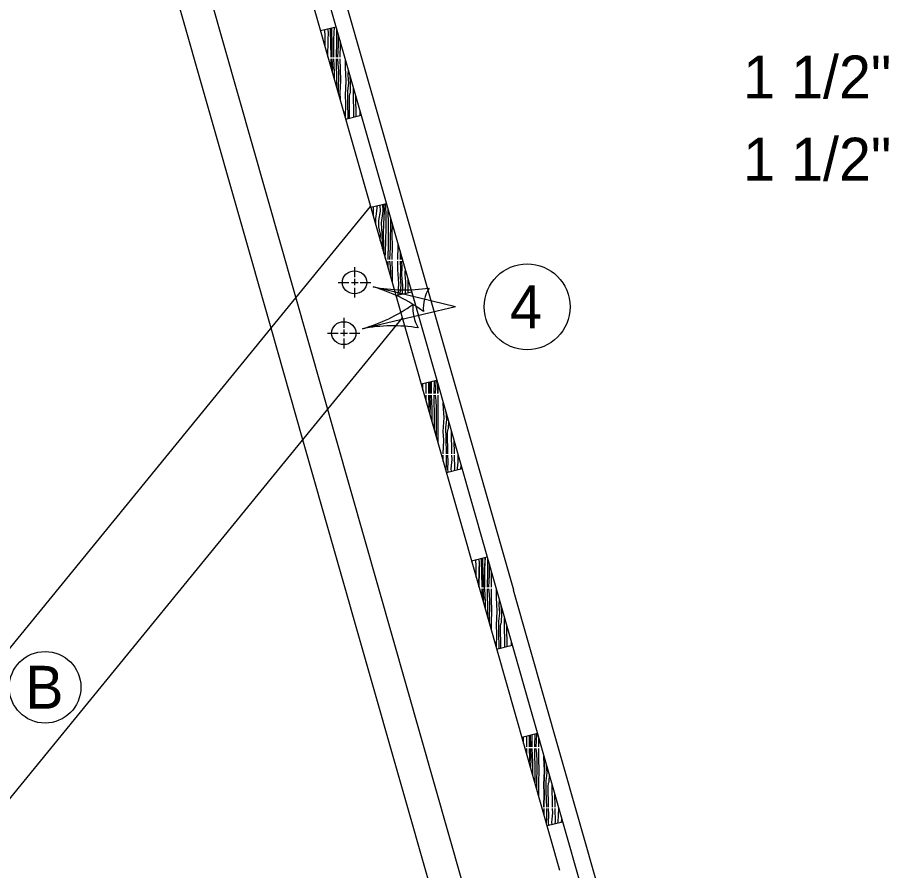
# Model space of a CAD drawing. Extents: x 49991.4 to 50021, y 49987.6 to 50011.4.
# Drawn here: x 50013.065 to 50014.286, y 49993.859 to 49995.05 of the extents above; entities that cross this region are included whole.
import ezdxf

# ---------------------------------------------------------------- set-up
doc = ezdxf.new("R2010")
doc.units = 0
for name, color, linetype in [('Level 1', 7, 'Continuous'), ('Level 2', 7, 'Continuous'), ('Level 3', 7, 'Continuous'), ('Level 33', 7, 'Continuous'), ('Level 4', 7, 'Continuous'), ('Level 5', 7, 'Continuous')]:
    doc.layers.add(name, color=color, linetype=linetype)

msp = doc.modelspace()

# ---------------------------------------------------------------- linework, layer by layer
at = {"layer": 'Level 1'}
for p, q in [((50013.7582, 49994.2501), (50013.1042, 49996.5446)), ((50013.6869, 49993.8419), (50012.9235, 49996.5211)), ((50013.7112, 49994.2501), (50013.0664, 49996.5131)), ((50013.4195, 49994.6162), (50013.1179, 49995.6741)), ((50013.6196, 49994.654), (50013.4039, 49995.411)), ((50013.4884, 49995.032), (50013.5102, 49995.0375)), ((50013.5235, 49994.9085), (50013.5453, 49994.9141)), ((50013.5587, 49994.7852), (50013.5804, 49994.7906)), ((50013.7346, 49994.2501), (50013.6148, 49994.6706)), ((50012.3964, 49993.3626), (50013.4541, 49994.6588)), ((50013.5938, 49994.6618), (50013.6157, 49994.6673)), ((50013.5938, 49994.6618), (50013.6157, 49994.6673)), ((50013.629, 49994.5384), (50013.6508, 49994.5439)), ((50012.5552, 49993.3474), (50013.4984, 49994.5032)), ((50013.6869, 49993.6773), (50013.4637, 49994.4605)), ((50013.6642, 49994.4149), (50013.686, 49994.4205)), ((50013.6992, 49994.2915), (50013.7211, 49994.297)), ((50013.7344, 49994.168), (50013.7562, 49994.1736)), ((50013.7696, 49994.0448), (50013.7913, 49994.0503)), ((50013.9188, 49993.6855), (50013.8228, 49994.0228)), ((50013.8047, 49993.9213), (50013.8265, 49993.9268)), ((50013.897, 49993.68), (50013.8257, 49993.9301))]:
    msp.add_line(p, q, dxfattribs=at)
for points in [[(50013.4988, 49994.9954), (50013.4992, 49995.0185), (50013.4994, 49995.0301), (50013.4987, 49995.0346)], [(50013.5018, 49995.0354), (50013.502, 49995.0307), (50013.5024, 49995.0149), (50013.5026, 49994.9949)], [(50013.5039, 49995.0359), (50013.5039, 49995.0307), (50013.5042, 49995.0149), (50013.5044, 49994.9949)], [(50013.5074, 49995.0368), (50013.5067, 49995.0201), (50013.5063, 49995.0053), (50013.5063, 49994.9949)], [(50013.5108, 49995.0354), (50013.5106, 49995.0175), (50013.5101, 49994.9949)], [(50013.4889, 49995.0303), (50013.4889, 49995.0322)], [(50013.4949, 49995.0091), (50013.4948, 49995.0247), (50013.4944, 49995.0329), (50013.4944, 49995.0336)], [(50013.5132, 49995.0267), (50013.5131, 49995.0119), (50013.512, 49994.9949)], [(50013.5158, 49995.0179), (50013.5158, 49995.0133), (50013.5156, 49994.9949)], [(50013.5158, 49995.0179), (50013.5158, 49995.0179)], [(50013.5026, 49994.9926), (50013.5031, 49994.98)], [(50013.5044, 49994.9926), (50013.505, 49994.9783), (50013.5048, 49994.9743)], [(50013.5063, 49994.9926), (50013.5068, 49994.9835), (50013.5075, 49994.9741), (50013.5075, 49994.9648)], [(50013.5101, 49994.9926), (50013.5108, 49994.9585), (50013.5108, 49994.9534)], [(50013.512, 49994.9926), (50013.5128, 49994.9856), (50013.5135, 49994.9753), (50013.5132, 49994.9447)], [(50013.5156, 49994.9926), (50013.5158, 49994.9783), (50013.5161, 49994.9618), (50013.5156, 49994.9455), (50013.5158, 49994.9358)], [(50013.5234, 49994.911), (50013.5238, 49994.9299), (50013.5234, 49994.9419), (50013.5244, 49994.9614), (50013.5234, 49994.9807), (50013.5234, 49994.9912)], [(50013.5271, 49994.9095), (50013.5267, 49994.9325), (50013.5265, 49994.9477), (50013.5279, 49994.9585), (50013.5269, 49994.97), (50013.5273, 49994.9774)], [(50013.5291, 49994.9101), (50013.5288, 49994.9403), (50013.5292, 49994.9438), (50013.5301, 49994.9457), (50013.5305, 49994.9586), (50013.5296, 49994.9692)], [(50013.5348, 49994.9114), (50013.5344, 49994.9473), (50013.5345, 49994.9517)], [(50013.5384, 49994.9124), (50013.5379, 49994.94)], [(50013.544, 49994.9184), (50013.544, 49994.9185)], [(50013.544, 49994.9139), (50013.544, 49994.9184)], [(50013.5622, 49994.7729), (50013.5624, 49994.7753), (50013.5622, 49994.7861)], [(50013.5656, 49994.7605), (50013.5655, 49994.7621), (50013.5656, 49994.7697), (50013.5668, 49994.7759), (50013.5674, 49994.7844), (50013.5674, 49994.7874)], [(50013.5718, 49994.7389), (50013.572, 49994.7476), (50013.5709, 49994.7538), (50013.5699, 49994.7579), (50013.5699, 49994.7667), (50013.572, 49994.7797), (50013.5717, 49994.7884)], [(50013.5751, 49994.7274), (50013.5751, 49994.7324), (50013.5746, 49994.7482), (50013.5735, 49994.7637), (50013.5759, 49994.7797), (50013.5755, 49994.7895)], [(50013.577, 49994.7208), (50013.5769, 49994.7324), (50013.5765, 49994.7482), (50013.5767, 49994.7619), (50013.5776, 49994.7797), (50013.5773, 49994.7898)], [(50013.5789, 49994.7141), (50013.579, 49994.7229), (50013.5794, 49994.7377), (50013.5802, 49994.7573), (50013.5802, 49994.7755), (50013.5795, 49994.785), (50013.5791, 49994.7904)], [(50013.5828, 49994.7124), (50013.5832, 49994.735), (50013.5834, 49994.7599), (50013.583, 49994.7818)], [(50013.583, 49994.7818), (50013.583, 49994.7819)], [(50013.586, 49994.7711), (50013.5858, 49994.7294), (50013.5847, 49994.7124)], [(50013.5886, 49994.7621), (50013.5882, 49994.7468), (50013.5884, 49994.7308), (50013.5882, 49994.7124)], [(50013.5963, 49994.7352), (50013.5964, 49994.7312), (50013.596, 49994.7124)], [(50013.5995, 49994.7237), (50013.5995, 49994.7237)], [(50013.5995, 49994.7237), (50013.5998, 49994.7124)], [(50013.583, 49994.7), (50013.5828, 49994.7101)], [(50013.5847, 49994.7101), (50013.5855, 49994.7031), (50013.5862, 49994.6929), (50013.586, 49994.689)], [(50013.5882, 49994.7101), (50013.5884, 49994.6959), (50013.5886, 49994.6801)], [(50013.596, 49994.7101), (50013.596, 49994.6982), (50013.5971, 49994.6789), (50013.5962, 49994.6624)], [(50013.5998, 49994.7101), (50013.6001, 49994.6987), (50013.5995, 49994.6877), (50013.6004, 49994.676), (50013.5992, 49994.6652), (50013.5992, 49994.6631)], [(50013.6018, 49994.7124), (50013.6018, 49994.7161)], [(50013.6029, 49994.664), (50013.6032, 49994.6761), (50013.6019, 49994.6907), (50013.6024, 49994.7013), (50013.6018, 49994.7101)], [(50013.6071, 49994.6652), (50013.6076, 49994.6814), (50013.6067, 49994.6907), (50013.6068, 49994.6956), (50013.6071, 49994.6973)], [(50013.586, 49994.689), (50013.586, 49994.689)], [(50013.6106, 49994.6659), (50013.6107, 49994.6825), (50013.6108, 49994.684)], [(50013.6314, 49994.5297), (50013.6314, 49994.5389)], [(50013.6357, 49994.54), (50013.6353, 49994.5249)], [(50013.6391, 49994.5409), (50013.6392, 49994.5249)], [(50013.6409, 49994.5413), (50013.641, 49994.5249)], [(50013.6431, 49994.5419), (50013.6428, 49994.5353), (50013.6428, 49994.5249)], [(50013.647, 49994.5428), (50013.6467, 49994.5249)], [(50013.6496, 49994.5435), (50013.6496, 49994.5419), (50013.6486, 49994.5249)], [(50013.6521, 49994.5249), (50013.6522, 49994.5387)], [(50013.6522, 49994.5387), (50013.6521, 49994.5249)], [(50013.6522, 49994.5387), (50013.6522, 49994.5387)], [(50013.6353, 49994.5227), (50013.6357, 49994.515)], [(50013.6392, 49994.5227), (50013.6397, 49994.5084), (50013.6391, 49994.5032)], [(50013.641, 49994.5227), (50013.6415, 49994.5084), (50013.6409, 49994.4966)], [(50013.6428, 49994.5227), (50013.6435, 49994.5135), (50013.644, 49994.5041), (50013.644, 49994.4859), (50013.644, 49994.4856)], [(50013.6467, 49994.5227), (50013.6472, 49994.4884), (50013.6472, 49994.4745)], [(50013.6486, 49994.5227), (50013.6495, 49994.5155), (50013.65, 49994.5053), (50013.6497, 49994.4657)], [(50013.6521, 49994.5227), (50013.6523, 49994.5084), (50013.6524, 49994.4919), (50013.6522, 49994.4754), (50013.6523, 49994.4594), (50013.6523, 49994.4565)], [(50013.6599, 49994.4409), (50013.6604, 49994.4598), (50013.6599, 49994.472), (50013.6609, 49994.4915), (50013.6599, 49994.5107), (50013.6599, 49994.5122)], [(50013.6635, 49994.4993), (50013.6644, 49994.4884), (50013.6631, 49994.4776), (50013.6632, 49994.4624), (50013.6638, 49994.4409)], [(50013.6409, 49994.4966), (50013.6409, 49994.4966)], [(50013.644, 49994.4855), (50013.644, 49994.4856)], [(50013.667, 49994.4868), (50013.6668, 49994.4756), (50013.6657, 49994.4738), (50013.6654, 49994.4703), (50013.6657, 49994.4409)], [(50013.667, 49994.4868), (50013.667, 49994.4868)], [(50013.671, 49994.4729), (50013.6713, 49994.4409)], [(50013.6747, 49994.46), (50013.6751, 49994.4409)], [(50013.6599, 49994.43), (50013.6599, 49994.4388)], [(50013.6638, 49994.4388), (50013.664, 49994.4273), (50013.6635, 49994.4174)], [(50013.6657, 49994.4388), (50013.6664, 49994.4299), (50013.6657, 49994.4192), (50013.6661, 49994.4154)], [(50013.6713, 49994.4388), (50013.672, 49994.4329), (50013.6708, 49994.4243), (50013.6705, 49994.4192), (50013.6709, 49994.4167)], [(50013.6751, 49994.4388), (50013.6755, 49994.42), (50013.6752, 49994.4178)], [(50013.6795, 49994.4188), (50013.6799, 49994.4206), (50013.6805, 49994.4291), (50013.6807, 49994.4388)], [(50013.6635, 49994.4173), (50013.6635, 49994.4174)], [(50013.6844, 49994.42), (50013.685, 49994.424)], [(50013.6998, 49994.2899), (50013.6998, 49994.2917)], [(50013.7058, 49994.2686), (50013.7057, 49994.2842), (50013.7053, 49994.2924), (50013.7053, 49994.2931)], [(50013.7059, 49994.2687), (50013.7058, 49994.2843), (50013.7054, 49994.2925), (50013.7054, 49994.293)], [(50013.7098, 49994.2548), (50013.7102, 49994.278), (50013.7103, 49994.2896), (50013.7096, 49994.2941)], [(50013.7097, 49994.2549), (50013.7101, 49994.278), (50013.7103, 49994.2896), (50013.7096, 49994.2941)], [(50013.7126, 49994.2949), (50013.713, 49994.2903), (50013.7134, 49994.2744), (50013.7136, 49994.2544)], [(50013.7127, 49994.2949), (50013.7129, 49994.2902), (50013.7133, 49994.2744), (50013.7135, 49994.2544)], [(50013.7148, 49994.2955), (50013.7148, 49994.2903), (50013.7152, 49994.2744), (50013.7154, 49994.2544)], [(50013.7148, 49994.2954), (50013.7148, 49994.2902), (50013.7151, 49994.2744), (50013.7153, 49994.2544)], [(50013.7183, 49994.2963), (50013.7176, 49994.2796), (50013.7172, 49994.2648), (50013.7172, 49994.2544)], [(50013.7173, 49994.2501), (50013.7173, 49994.2649), (50013.7177, 49994.2796), (50013.7184, 49994.2964)], [(50013.7217, 49994.2949), (50013.7215, 49994.277), (50013.721, 49994.2544)], [(50013.7217, 49994.2949), (50013.7216, 49994.277), (50013.7211, 49994.2544)], [(50013.7241, 49994.2862), (50013.724, 49994.2714), (50013.7229, 49994.2544)], [(50013.7242, 49994.2863), (50013.7241, 49994.2714), (50013.723, 49994.2544)], [(50013.7267, 49994.2774), (50013.7267, 49994.2728), (50013.7265, 49994.2544)], [(50013.7267, 49994.2774), (50013.7268, 49994.2728), (50013.7266, 49994.2544)], [(50013.7267, 49994.2774), (50013.7267, 49994.2774)], [(50013.7267, 49994.2774), (50013.7267, 49994.2774)], [(50013.7135, 49994.2521), (50013.714, 49994.2395)], [(50013.7136, 49994.2523), (50013.7137, 49994.2501)], [(50013.7153, 49994.2521), (50013.7159, 49994.2378), (50013.7157, 49994.2338)], [(50013.7154, 49994.2523), (50013.7155, 49994.2501)], [(50013.7172, 49994.2521), (50013.7177, 49994.243), (50013.7184, 49994.2336), (50013.7184, 49994.2243)], [(50013.721, 49994.2521), (50013.7217, 49994.218), (50013.7217, 49994.2129)], [(50013.7211, 49994.2523), (50013.7211, 49994.2501)], [(50013.7229, 49994.2521), (50013.7237, 49994.2451), (50013.7244, 49994.2348), (50013.7241, 49994.2042)], [(50013.723, 49994.2523), (50013.7233, 49994.2501)], [(50013.7265, 49994.2521), (50013.7267, 49994.2378), (50013.727, 49994.2213), (50013.7265, 49994.205), (50013.7267, 49994.1953)], [(50013.7266, 49994.2523), (50013.7266, 49994.2501)], [(50013.7343, 49994.1705), (50013.7347, 49994.1894), (50013.7343, 49994.2014), (50013.7353, 49994.2209), (50013.7343, 49994.2402), (50013.7343, 49994.2507)], [(50013.7344, 49994.2501), (50013.7344, 49994.2507)], [(50013.738, 49994.169), (50013.7376, 49994.192), (50013.7374, 49994.2072), (50013.7388, 49994.218), (50013.7378, 49994.2295), (50013.7382, 49994.2369)], [(50013.74, 49994.1696), (50013.7397, 49994.1998), (50013.7401, 49994.2033), (50013.741, 49994.2052), (50013.7414, 49994.2181), (50013.7405, 49994.2287)], [(50013.7457, 49994.1709), (50013.7453, 49994.2068), (50013.7454, 49994.2112)], [(50013.7493, 49994.1719), (50013.7488, 49994.1995)], [(50013.7549, 49994.1779), (50013.7549, 49994.178)], [(50013.7549, 49994.1734), (50013.7549, 49994.1779)], [(50013.7762, 49994.0465), (50013.7759, 49994.0313)], [(50013.7796, 49994.0473), (50013.7797, 49994.0313)], [(50013.7814, 49994.0478), (50013.7815, 49994.0313)], [(50013.7836, 49994.0483), (50013.7833, 49994.0417), (50013.7833, 49994.0313)], [(50013.7876, 49994.0494), (50013.7872, 49994.0313)], [(50013.7902, 49994.05), (50013.7902, 49994.0483), (50013.7892, 49994.0313)], [(50013.772, 49994.0361), (50013.7719, 49994.0454)], [(50013.7928, 49994.0451), (50013.7926, 49994.0313)], [(50013.7928, 49994.0451), (50013.7928, 49994.0451)], [(50013.7759, 49994.0291), (50013.7762, 49994.0215)], [(50013.7797, 49994.0291), (50013.7802, 49994.0146), (50013.7796, 49994.0096)], [(50013.7815, 49994.0291), (50013.782, 49994.0146), (50013.7815, 49994.0029)], [(50013.7833, 49994.0291), (50013.784, 49994.02), (50013.7846, 49994.0105), (50013.7846, 49993.9923), (50013.7846, 49993.992)], [(50013.7872, 49994.0291), (50013.7879, 49993.9949), (50013.7878, 49993.9808)], [(50013.7892, 49994.0291), (50013.79, 49994.0219), (50013.7905, 49994.0116), (50013.7902, 49993.9721)], [(50013.7926, 49994.0291), (50013.7928, 49994.0146), (50013.7931, 49993.9983), (50013.7927, 49993.9818), (50013.7928, 49993.9658), (50013.7928, 49993.9629)], [(50013.8004, 49993.9473), (50013.8009, 49993.9662), (50013.8004, 49993.9784), (50013.8014, 49993.9979), (50013.8004, 49994.0171), (50013.8004, 49994.0184)], [(50013.8004, 49994.0184), (50013.8004, 49994.0171), (50013.8014, 49993.9979), (50013.8004, 49993.9784), (50013.8009, 49993.9662), (50013.8004, 49993.9473)], [(50013.7815, 49994.0029), (50013.7815, 49994.0029)], [(50013.8043, 49993.9473), (50013.8037, 49993.9688), (50013.8036, 49993.984), (50013.8051, 49993.9949), (50013.804, 49994.0058)], [(50013.7846, 49993.9919), (50013.7846, 49993.992)], [(50013.8077, 49993.9932), (50013.8073, 49993.982), (50013.8063, 49993.9802), (50013.8058, 49993.9766), (50013.8062, 49993.9473)], [(50013.8077, 49993.9932), (50013.8077, 49993.9932)], [(50013.8115, 49993.9793), (50013.8118, 49993.9473)], [(50013.8152, 49993.9664), (50013.8156, 49993.9473)], [(50013.8004, 49993.9451), (50013.8004, 49993.9364)], [(50013.804, 49993.9236), (50013.8045, 49993.9336), (50013.8043, 49993.9451)], [(50013.8062, 49993.9451), (50013.8069, 49993.9362), (50013.8063, 49993.9256), (50013.8066, 49993.9218)], [(50013.8118, 49993.9451), (50013.8125, 49993.9391), (50013.8113, 49993.9305), (50013.811, 49993.9256), (50013.8113, 49993.923)], [(50013.8156, 49993.9451), (50013.816, 49993.9264), (50013.8158, 49993.9242)], [(50013.82, 49993.9252), (50013.8204, 49993.927), (50013.8209, 49993.9355), (50013.8212, 49993.9451)], [(50013.8248, 49993.9264), (50013.8255, 49993.9303)], [(50013.804, 49993.9236), (50013.804, 49993.9236)]]:
    msp.add_lwpolyline(points, dxfattribs=at)
for centre in [(50013.5359, 49994.6803), (50013.5209, 49994.6094)]:
    msp.add_ellipse(centre, major_axis=(0.017, 0), ratio=0.940299, dxfattribs=at)
at = {"layer": 'Level 2'}
for centre, radius in [((50013.777, 49994.6462), 0.06), ((50013.1037, 49994.1146), 0.05)]:
    msp.add_circle(centre, radius, dxfattribs=at)
at = {"layer": 'Level 3'}
for q in [(50013.5621, 49994.674), (50013.5471, 49994.6156)]:
    msp.add_line((50013.677, 49994.6462), q, dxfattribs=at)
for centre, radius, start, end in [((50013.501, 49994.4602), 0.2223, 53.8547, 74.0382), ((50013.6057, 49994.9029), 0.233, 259.226, 278.4759), ((50013.6867, 49994.6438), 0.0548, 148.5375, 184.2599), ((50013.4826, 49994.8395), 0.233, 286.0826, 305.3324), ((50013.6719, 49994.645), 0.0548, 175.3941, 211.1164), ((50013.5891, 49994.3973), 0.2223, 80.7113, 100.8948)]:
    msp.add_arc(centre, radius, start, end, dxfattribs=at)
at = {"layer": 'Level 33'}
for p, q in [((50013.8228, 49993.8588), (50013.7112, 49994.2501)), ((50013.8306, 49993.9135), (50013.7346, 49994.2501)), ((50013.8228, 49994.023), (50013.7581, 49994.2501))]:
    msp.add_line(p, q, dxfattribs=at)
at = {"layer": 'Level 4'}
for p, q in [((50013.4541, 49994.6588), (50013.5583, 49994.7865)), ((50013.4984, 49994.5032), (50013.6027, 49994.6309)), ((50013.4637, 49994.4605), (50013.4194, 49994.6162))]:
    msp.add_line(p, q, dxfattribs=at)
at = {"layer": 'Level 5'}
for p, q in [((50013.5358, 49994.7015), (50013.5358, 49994.6877)), ((50013.5358, 49994.6854), (50013.5358, 49994.6762)), ((50013.5132, 49994.6803), (50013.5279, 49994.6803)), ((50013.5315, 49994.6803), (50013.5409, 49994.6803)), ((50013.5358, 49994.6728), (50013.5358, 49994.659)), ((50013.5438, 49994.6803), (50013.5585, 49994.6803)), ((50013.5208, 49994.6306), (50013.5208, 49994.6168)), ((50013.4982, 49994.6094), (50013.5129, 49994.6094)), ((50013.5165, 49994.6094), (50013.5259, 49994.6094)), ((50013.5208, 49994.6145), (50013.5208, 49994.6053)), ((50013.5288, 49994.6094), (50013.5435, 49994.6094)), ((50013.5208, 49994.6019), (50013.5208, 49994.5881))]:
    msp.add_line(p, q, dxfattribs=at)

# ---------------------------------------------------------------- texts
at = {"layer": 'Level 2'}
for s, p in [('1 1/2" [38.1]', (50014.0786, 49994.9372)), ('1 1/2" [38.1]', (50014.0786, 49994.8224)), ('4', (50013.753, 49994.6162)), ('B', (50013.0759, 49994.0846))]:
    msp.add_text(s, height=0.06, dxfattribs=at).set_placement(p)

doc.saveas('drawing.dxf')
